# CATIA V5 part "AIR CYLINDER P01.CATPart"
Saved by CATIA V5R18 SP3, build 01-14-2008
Part number: AIR CYLINDER 02
Bounding box of the stored display mesh (mm): x -75 to 75, y -74.992 to 74.992, z 0 to 418
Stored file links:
  E:\#00 CATIA V5 Movie\#03 CATIA V5 Data\#07 KIN\Balance Unit (1)\AIR CYLINDER P01.CATPart
  CATDrawing1.CATDrawing
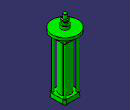
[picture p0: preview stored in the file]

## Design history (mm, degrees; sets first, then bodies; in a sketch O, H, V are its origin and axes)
Body1 "PartBody" (main body)
  Solid1: solid without history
